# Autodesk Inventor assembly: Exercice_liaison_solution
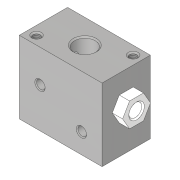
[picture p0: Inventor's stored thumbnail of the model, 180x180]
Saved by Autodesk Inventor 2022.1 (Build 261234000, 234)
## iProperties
Created: 2021-07
Part Number: Exercice_liaison_solution
Document SubType Name: Assembly
Designer: Fabian
Author: Fabian
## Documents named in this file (3)
- C:\Users\Fabian\Google Drive\01_Giup\01_Clients\07_ENI\Manuscrit\Fichiers_exercice\Chapitre_06\Exercice_liaison\Exercice_liaison_solution.iam
- C:\Users\Fabian\Google Drive\01_Giup\01_Clients\07_ENI\Manuscrit\Fichiers_exercice\Chapitre_06\Exercice_liaison\Corps_de_capteur.ipt
- C:\Users\Fabian\Google Drive\01_Giup\01_Clients\07_ENI\Manuscrit\Fichiers_exercice\Chapitre_06\Exercice_liaison\Raccord.iam
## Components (2 placed, 2 different names)
1. Corps_de_capteur:1 — Rotation:1
2. Raccord:1 [sub-assembly] — Rotation:1
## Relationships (1: RevoluteJoint 1)
- Rotation:1 [RevoluteJoint]: Corps_de_capteur:1 ↔ Raccord:1
